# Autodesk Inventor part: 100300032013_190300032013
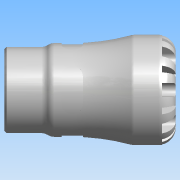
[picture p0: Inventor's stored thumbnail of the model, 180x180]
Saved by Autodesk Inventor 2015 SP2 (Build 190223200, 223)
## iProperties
Created: 2016-12
Part Number: 100300032013_190300032013
Material: PVC-Piping
Description: PLASSON FEMALE ADAPTOR 32X1.1/4" SERIES 1
Document SubType Name: Modeling
Designer: KIM
Mass: 664.223 g
Surface Area: 733.008 cm^2
Volume: 474.445 cm^3
Density: 1.4 g/cm^3
Appearance: Smooth - White
Author: KIM
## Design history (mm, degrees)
derived "1003.ipt"
feature "Solid1::1003.ipt"
tag "TaggingFeature1"
body "Solid1"
other parameters: "d1" = 22.68, "d2" = 32, "d4" = 58, "d6" = 54, "d8" = 49.3, "d13" = 7.2, "d14" = 7.2, "d15" = 0, "d17" = 360 deg, "d19" = 8 deg, "d20" = 0.64, "d21" = 0.64, "d22" = 8 deg, "d24" = 0, "d26" = 360 deg, "d32" = 5.8, "d33" = 5.8, "d39" = 1.16856, "d42" = 38.952, "d43" = 45.24, "d46" = 2.66667, "d47" = 24, "d48" = 37.0044, "d50" = 3.96, "d51" = 0.58, "d54" = 11.2, "d55" = 7.04, "d57" = 14.112, "d58" = 0, "d68" = 360 deg, "d72" = 0.64, "d74" = 0, "d76" = 9.52, "d_" = 32, "E_" = 58, "l_" = 54, "Rp" = 38.952, "l_2" = 24, "d9" = 9, "d11" = 58, "d49" = 12
